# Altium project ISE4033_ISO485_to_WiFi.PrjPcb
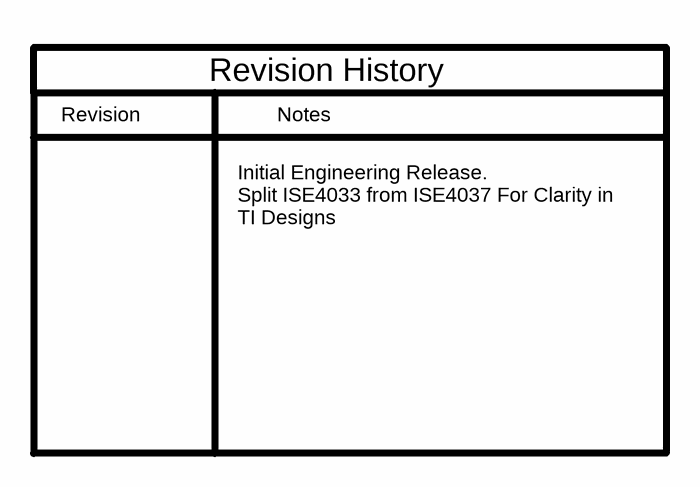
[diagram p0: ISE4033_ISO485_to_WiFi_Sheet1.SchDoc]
TID: TIDA-00486; TechSupport: http://www.ti.com/support; SCH_Rev: E1; PRJ_Title: Isolated RS-485 To Wi-Fi Bridge with 24 VAC Power; PRJ_Number: ISE4033; PRJ_Engineer: M. Knapp; PRJ_Customer: Public Release; PCB_Rev: E1; PCB_Layout: Krypton Solutions/RS; EVM_Orderable: N/A; CopyrightYear: 2015
6 sheets, 129 parts. Net scope: global (net labels, ports and power ports of the same name join across sheets).
Board file: ISE4033_ISO485_to_WiFi.PcbDoc
Sheets:
  ISE4033_ISO485_to_WiFi_Sheet1.SchDoc
  ISE4033_ISO485_to_WiFi_Sheet2.SchDoc
  ISE4033_ISO485_to_WiFi_Sheet3.SchDoc
  ISE4033_ISO485_to_WiFi_Sheet4.SchDoc
  ISE4033_ISO485_to_WiFi_Sheet5.SchDoc
  ISE4033E2_Sheet6.SchDoc

## Sheet ISE4033_ISO485_to_WiFi_Sheet1.SchDoc
size 431 x 279 mm; Date: Not shown in title block; ApprovedBy: Not shown in title block; CheckedBy: Not shown in title block; Author: Not shown in title block; CompanyName: Not shown in title block; Engineer: Not shown in title block; Organization: Not shown in title block; Address1: Not shown in title block; Address2: Not shown in title block; Address3: Not shown in title block; Address4: Not shown in title block; DocumentNumber: 1; Revision: Use project parameter SCH_Rev; SheetNumber: 1; SheetTotal: 6; PageSetup: Record=PageOptions¦CenterHorizontal=True¦CenterVertical=True¦PrintScale=1.00¦XCorrection=1.00¦YCorrection=1.00¦PrintKind=0¦BorderSize=5000000¦LeftOffset=0¦BottomOffset=0¦Orientation=2¦PaperLength=1000¦PaperWidth=1000¦Scale=100¦PaperSource=15¦PrintQuality=-3¦MediaType=1¦DitherType=10¦PrintScaleMode=1¦PaperKind=Tabloid (11 x 17")¦PaperIndex=17

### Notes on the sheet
- Revision
- Notes
- Revision History
- Initial Engineering Release.
  Split ISE4033 from ISE4037 For Clarity in
  TI Designs

## Sheet ISE4033_ISO485_to_WiFi_Sheet2.SchDoc
size 431 x 279 mm; Date: Not shown in title block; ApprovedBy: Not shown in title block; CheckedBy: Not shown in title block; Author: Not shown in title block; CompanyName: Not shown in title block; Engineer: Not shown in title block; Organization: Not shown in title block; Address1: Not shown in title block; Address2: Not shown in title block; Address3: Not shown in title block; Address4: Not shown in title block; DocumentNumber: 1; Revision: Use project parameter SCH_Rev; SheetNumber: 2; SheetTotal: 6; PageSetup: Record=PageOptions¦CenterHorizontal=True¦CenterVertical=True¦PrintScale=1.00¦XCorrection=1.00¦YCorrection=1.00¦PrintKind=0¦BorderSize=5000000¦LeftOffset=0¦BottomOffset=0¦Orientation=2¦PaperLength=1000¦PaperWidth=1000¦Scale=100¦PaperSource=15¦PrintQuality=-3¦MediaType=1¦DitherType=10¦PrintScaleMode=1¦PaperKind=Tabloid (11 x 17")¦PaperIndex=17
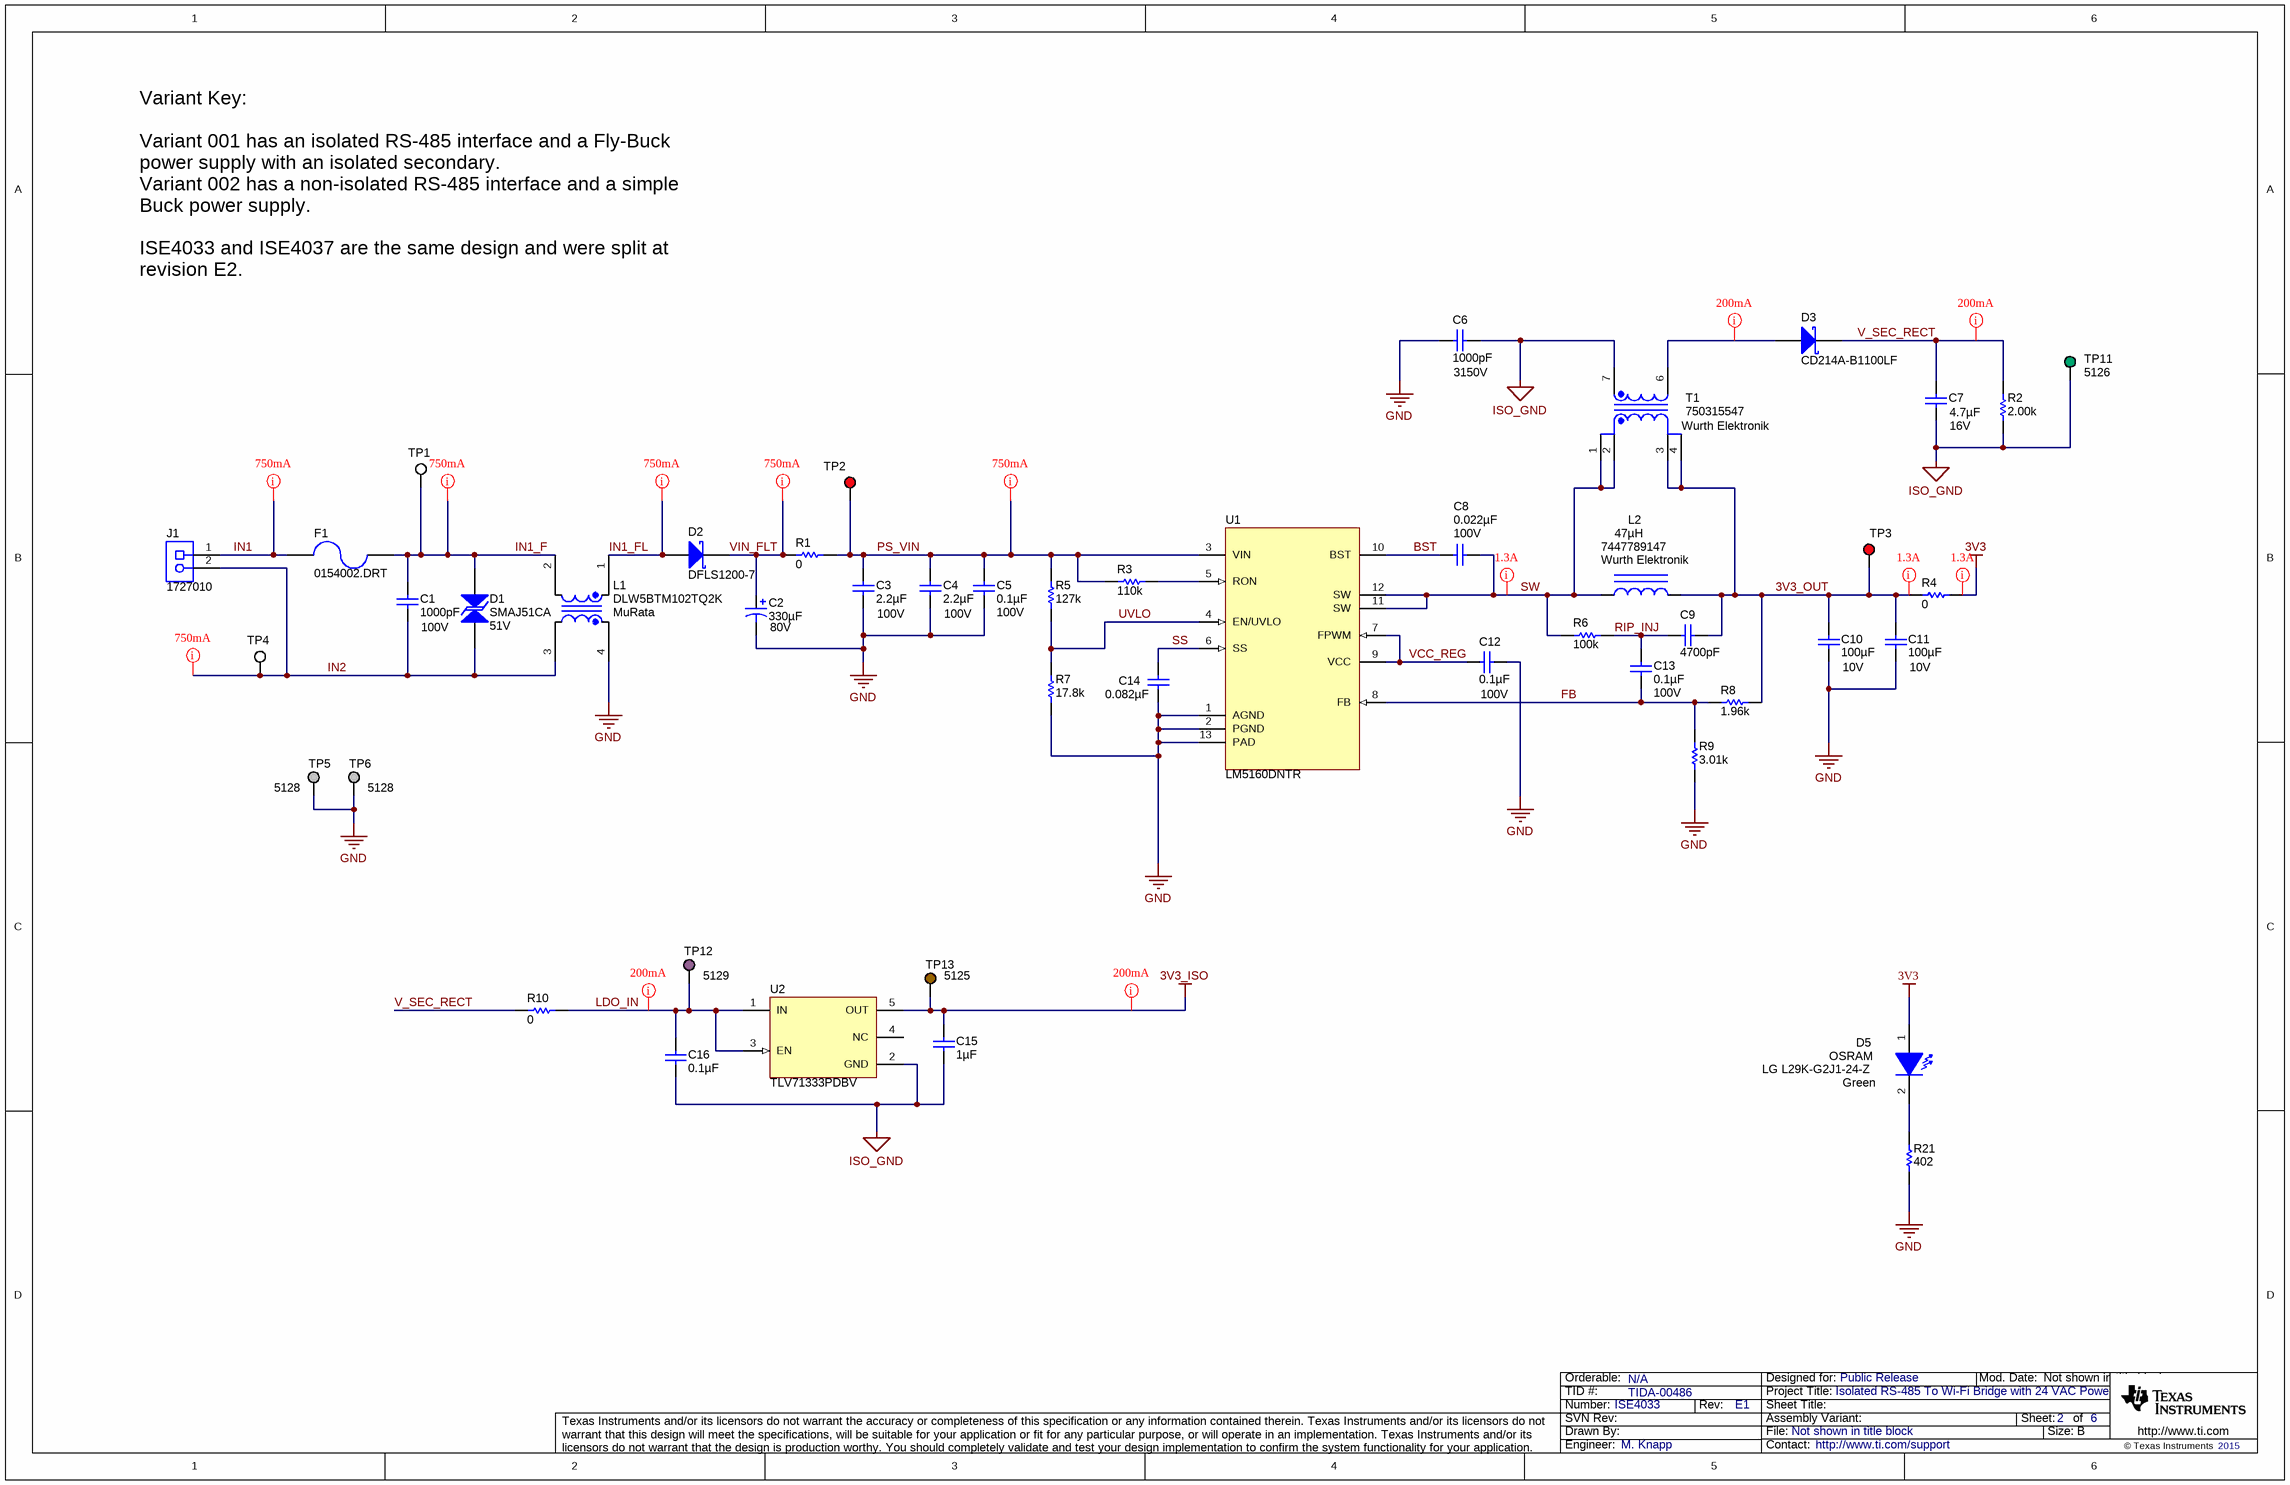
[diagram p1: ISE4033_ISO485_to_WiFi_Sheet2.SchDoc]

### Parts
C1  ValueDisplayed: 1000pF  Value2: 100V  [0603]  (hidden comment: 06031C102KAT2A)
C2  ValueDisplayed: 330µF  Value2: 80V  [SM_RADIAL_J16]  (hidden comment: EEV-FK1K331M)
C3  ValueDisplayed: 2.2µF  Value2: 100V  [1210]  (hidden comment: C1210C225K1RACTU)
C4  ValueDisplayed: 2.2µF  Value2: 100V  [1210]  (hidden comment: C1210C225K1RACTU)
C5  ValueDisplayed: 0.1µF  Value2: 100V  [0805_HV]  (hidden comment: C0805C104K1RACTU)
C6  ValueDisplayed: 1000pF  Value2: 3150V  [CAPRD750W60D700H1000]  (hidden comment: DEBE33F102ZC3B)
C7  ValueDisplayed: 4.7µF  Value2: 16V  [1206]  (hidden comment: C3216X7R1C475K)
C8  ValueDisplayed: 0.022µF  Value2: 100V  [0805_HV]  (hidden comment: 08051C223KAT2A)
C9  ValueDisplayed: 4700pF  [0603]  (hidden comment: 06031C472KAT2A)
C10  ValueDisplayed: 100µF  Value2: 10V  [1210_280]  (hidden comment: C1210C107M8PACTU)
C11  ValueDisplayed: 100µF  Value2: 10V  [1210_280]  (hidden comment: C1210C107M8PACTU)
C12  ValueDisplayed: 0.1µF  Value2: 100V  [0805_HV]  (hidden comment: C0805C104K1RACTU)
C13  ValueDisplayed: 0.1µF  Value2: 100V  [0805_HV]  (hidden comment: C0805C104K1RACTU)
C14  ValueDisplayed: 0.082µF  [0805_HV]  (hidden comment: C0805C823K1RACTU)
C15  ValueDisplayed: 1µF  [0603]  (hidden comment: GRM188R71A105KA61D)
C16  ValueDisplayed: 0.1µF  [0402]  (hidden comment: GRM155R71A104KA01D)
D1  SMAJ51CA  value 51V  [SMA]
D2  DFLS1200-7  [powerDI123]
D3  CD214A-B1100LF  [SMA]
D5  value Green  Manufacturer: OSRAM  [LG L29K_GREEN]  (hidden comment: LG L29K-G2J1-24-Z)
F1  0154002.DRT  [FUSE_154]
J1  1727010  [PhoenixConact_1727010]
L1  DLW5BTM102TQ2K  Manufacturer: MuRata  [DLW5BT_TQ2]
L2  7447789147  Manufacturer: Wurth Elektronik  ValueDisplayed: 47µH  [WE-PD-S]
R1  ValueDisplayed: 0  [2010]  (hidden comment: CRCW20100000Z0EF)
R2  ValueDisplayed: 2.00k  [0402]  (hidden comment: CRCW04022K00FKED)
R3  ValueDisplayed: 110k  [0402]  (hidden comment: CRCW0402110KFKED)
R4  ValueDisplayed: 0  [2010]  (hidden comment: CRCW20100000Z0EF)
R5  ValueDisplayed: 127k  [0402]  (hidden comment: CRCW0402127KFKED)
R6  ValueDisplayed: 100k  [0402]  (hidden comment: CRCW0402100KFKED)
R7  ValueDisplayed: 17.8k  [0402]  (hidden comment: CRCW040217K8FKED)
R8  ValueDisplayed: 1.96k  [0402]  (hidden comment: CRCW04021K96FKED)
R9  ValueDisplayed: 3.01k  [0402]  (hidden comment: CRCW04023K01FKED)
R10  ValueDisplayed: 0  [0603]  (hidden comment: CRCW06030000Z0EA)
R21  ValueDisplayed: 402  [0402]  (hidden comment: CRCW0402402RFKED)
T1  750315547  Manufacturer: Wurth Elektronik  [Wurth_750315547_48]
TP1  5002  [Keystone5002]  (value not drawn)
TP2  5000  [Keystone5000]  (value not drawn)
TP3  5000  [Keystone5000]  (value not drawn)
TP4  5002  [Keystone5002]  (value not drawn)
TP5  5128  [Keystone5128]
TP6  5128  [Keystone5128]
TP11  5126  [Keystone5126]
TP12  5129  [Keystone5129]
TP13  5125  [Keystone5125]
U1  LM5160DNTR  [DNT0012B]
U2  TLV71333PDBV  [DBV0005A_N]

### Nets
3V3: D5.1(A) R4.2
3V3_ISO: C15.1 TP13.1 U2.5(OUT)
GND: C2.2(-) C3.2 C4.2 C5.2 C6.2 C10.2 C11.2 C12.2 C14.2 L1.4 R7.1 R9.1 R21.1 TP5.1 TP6.1 U1.1(AGND) U1.2(PGND) U1.13(PAD)
ISO_GND: C6.1 C7.2 C15.2 C16.2 R2.1 T1.7 TP11.1 U2.2(GND)
3V3_OUT: C9.1 C10.1 C11.1 L2.2 R4.1 R8.2 T1.3 T1.4 TP3.1
BST: C8.2 U1.10(BST)
FB: C13.2 R8.1 R9.2 U1.8(FB)
IN1: F1.2 J1.1
IN1_F: C1.1 D1.2 F1.1 L1.2 TP1.1
IN1_FL: D2.2(A) L1.1
IN2: C1.2 D1.1 J1.2 L1.3 TP4.1
LDO_IN: C16.1 R10.2 TP12.1 U2.1(IN) U2.3(EN)
PS_VIN: C3.1 C4.1 C5.1 R1.2 R3.1 R5.2 TP2.1 U1.3(VIN)
RIP_INJ: C9.2 C13.1 R6.2
SS: C14.1 U1.6(SS)
SW: C8.1 L2.1 R6.1 T1.1 T1.2 U1.11(SW) U1.12(SW)
UVLO: R5.1 R7.2 U1.4(EN/UVLO)
V_SEC_RECT: C7.1 D3.1(K) R2.2 R10.1
VCC_REG: C12.1 U1.7(FPWM) U1.9(VCC)
VIN_FLT: C2.1(+) D2.1(K) R1.1
NetD3_2: D3.2(A) T1.6
NetD5_2: D5.2(K) R21.2
NetR3_2: R3.2 U1.5(RON)

Not connected (* = marked no-connect by the designer): U2 4(NC)

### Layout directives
750mA: 750mA: 3V3, 3V3_ISO, 3V3_OUT, IN1, IN1_F, IN1_FL, IN2, LDO_IN, NetD3_2, PS_VIN, SW, V_SEC_RECT, VIN_FLT

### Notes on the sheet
- Variant Key:
  Variant 001 has an isolated RS-485 interface and a Fly-Buck power supply with an isolated secondary.
  Variant 002 has a non-isolated RS-485 interface and a simple Buck power supply.
  ISE4033 and ISE4037 are the same design and were split at revision E2.

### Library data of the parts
C1 = 06031C102KAT2A: CAP, CERM, 1000 pF, 100 V, +/- 10%, X7R, 0603; Manufacturer: AVX; Polarized: N; CompType: Capacitor; Value: 1000pF; U/M: EA; Cap_F: 0.000000001; Tolerance_%: 10; ESR_ohm: 0.276; Value1: 0.276 ohm; VDC_V: 100; TaMin_C: -55; TaMax_C: 125
C2 = EEV-FK1K331M: CAP, AL, 330 µF, 80 V, +/- 20%, 0.17 ohm, SMD; Manufacturer: Panasonic; Polarized: Y; CompType: Capacitor; Value: 330uF; U/M: EA; Cap_F: 0.00033; Tolerance_%: 20; VDC_V: 80; ESR_ohm: 0.17; IRMS_A: 0.793; TaMin_C: -55; TaMax_C: 105; Cap_Case: J16
C3 C4 = C1210C225K1RACTU: CAP, CERM, 2.2 µF, 100 V, +/- 10%, X7R, 1210; Manufacturer: Kemet; Polarized: N; CompType: Capacitor; Value: 2.2uF; U/M: EA; Cap_F: 0.0000022; Tolerance_%: 10; Value1: Unknown; VDC_V: 100; TaMin_C: -55; TaMax_C: 125
C5 C12 C13 = C0805C104K1RACTU: CAP, CERM, 0.1 µF, 100 V, +/- 10%, X7R, 0805; Manufacturer: Kemet; Polarized: N; CompType: Capacitor; Value: 0.1uF; U/M: EA; Cap_F: 0.0000001; Tolerance_%: 10; ESR_ohm: 0.064; Value1: 0.064 ohm; VDC_V: 100; IRMS_A: 1.64; TaMin_C: -55; TaMax_C: 125; Cap_Case: 0805
C6 = DEBE33F102ZC3B: CAP, CERM, 1000 pF, 3150 V, +80/-20%, E, Radial Disc D7x6mm; Manufacturer: MuRata; Polarized: N; CompType: Capacitor; Value: 1000pF; U/M: EA; Cap_F: 0.000000001; Tolerance_%: 80; Value1: Unknown; VDC_V: 3150; TaMin_C: -25; TaMax_C: 85; Cap_Case: Disc, 7x6mm
C7 = C3216X7R1C475K: CAP, CERM, 4.7 µF, 16 V, +/- 10%, X7R, 1206; Manufacturer: TDK; Polarized: N; CompType: Capacitor; Value: 4.7uF; U/M: EA; Cap_F: 0.0000047; Tolerance_%: 10; ESR_ohm: 0.0036; Value1: 0.0036 ohm; VDC_V: 16; IRMS_A: 2; TaMin_C: -55; TaMax_C: 125
C8 = 08051C223KAT2A: CAP, CERM, 0.022 µF, 100 V, +/- 10%, X7R, 0805; Manufacturer: AVX; Polarized: N; CompType: Capacitor; Value: 0.022uF; U/M: EA; Cap_F: 0.000000022; Tolerance_%: 10; ESR_ohm: 0.052; Value1: 0.052 ohm; VDC_V: 100; TaMin_C: -55; TaMax_C: 125; Cap_Case: 0805
C9 = 06031C472KAT2A: CAP, CERM, 4700 pF, 100 V, +/- 10%, X7R, 0603; Manufacturer: AVX; Polarized: N; CompType: Capacitor; Value: 4700pF; U/M: EA; Cap_F: 0.0000000047; Tolerance_%: 10; ESR_ohm: 0.136; Value1: 0.136 ohm; VDC_V: 100; Value2: 100V; TaMin_C: -55; TaMax_C: 125
C10 C11 = C1210C107M8PACTU: CAP, CERM, 100 µF, 10 V, +/- 20%, X5R, 1210; Manufacturer: Wurth Elektronik; Polarized: N; CompType: Capacitor; Value: 100uF; U/M: EA; Cap_F: 0.0001; Tolerance_%: 20; Value1: Unknown; VDC_V: 10; TaMin_C: -55; TaMax_C: 85; Cap_Case: 1210
C14 = C0805C823K1RACTU: CAP, CERM, 0.082 µF, 100 V, +/- 10%, X7R, 0805; Manufacturer: Kemet; Polarized: N; CompType: Capacitor; Value: 0.082uF; U/M: EA; Cap_F: 0.000000082; Tolerance_%: 10; ESR_ohm: 0.071; Value1: 0.071 ohm; VDC_V: 100; Value2: 100V; IRMS_A: 1.44; TaMin_C: -55; TaMax_C: 125; Cap_Case: 0805
C15 = GRM188R71A105KA61D: CAP, CERM, 1 µF, 10 V, +/- 10%, X7R, 0603; Manufacturer: MuRata; Polarized: N; CompType: Capacitor; Value: 1uF; U/M: EA; Cap_F: 0.000001; Tolerance_%: 10; ESR_ohm: 0.011; Value1: 0.011 ohm; Value2: 10V; TaMin_C: -55; TaMax_C: 125
C16 = GRM155R71A104KA01D: CAP, CERM, 0.1 µF, 10 V, +/- 10%, X7R, 0402; Manufacturer: MuRata; Polarized: N; CompType: Capacitor; Value: 0.1uF; U/M: EA; Cap_F: 0.0000001; Tolerance_%: 10; Value1: Unknown; Value2: 10V; TaMin_C: -55; TaMax_C: 125
D1 = SMAJ51CA: Diode, TVS, Bi, 51 V, 400 W, SMA; Manufacturer: Littelfuse; U/M: EA; Power_W: 400; Vr_V: 51; Value1: 400W; RJA_CperW: 120
D2 = DFLS1200-7: Diode, Schottky, 200 V, 1 A, PowerDI123; Manufacturer: Diodes Inc.; U/M: EA; Vf_V: 0.85; Value: 200V; Value1: 1A; Value2: 0.85V; Io_A: 1; Vr_V: 200; TJmax_C: 175; RJC_CperW: 7
D3 = CD214A-B1100LF: Diode, Schottky, 100 V, 1 A, SMA; Manufacturer: Bourns; U/M: EA; Vf_V: 0.79; Value: 100V; Value1: 1A; Value2: 0.79V; Io_A: 1; Vr_V: 100; TJmax_C: 125; RJC_CperW: 25
D5 = LG L29K-G2J1-24-Z: LED, Green, SMD; Vf_V: 1.7; Value2: 1.7V; Io_A: 0.002; Tjmax_C: 110; Value1: W; U/M: EA
F1 = 0154002.DRT: Fuse, 2 A, 125 V, SMD; Manufacturer: Littelfuse; U/M: EA; VDC_V: 125; Interrupt_AC: 50; Irating_A: 2; Rtyp_Ohm: 0.0625; MeltingTyp: 8.2; Soldering_Reflow_MaxTemp_C: 260; Soldering_Reflow_MaxTime_s: 40
J1 = 1727010: Conn Term Block, 2POS, 3.81mm, TH; Manufacturer: Phoenix Contact; SymbolCreator: a0412235; CompType: Terminal Block; U/M: EA; Value: 2x1
L1 = DLW5BTM102TQ2K: Coupled inductor, 2.5 A, 0.034 ohm, SMD; SymbolCreator: a0412235; Isat: 2.5; DCR_ohm: 0.034
L2 = 7447789147: Inductor, Shielded Drum Core, Ferrite, 47 µH, 0.85 A, 0.315 ohm, SMD; Ind_H: 47.0E-6; Value: 47uH; Imax_A: 0.85; Irms: 0.85A @ 40C rise; Isat: 1A @ 10% inductance drop; DCR_ohm: 0.315; Value2: 0.85A
R1 R4 = CRCW20100000Z0EF: RES, 0, 5%, 0.75 W, 2010; Manufacturer: Vishay-Dale; CompType: Resistor; Value: 0; Value_Code: 0000; Tolerance_%: 5; Power_W: 0.75; Value2: 0.75W; TempCo: ppm/C; EIA_Code: E24; U/M: EA
R2 = CRCW04022K00FKED: RES, 2.00 k, 1%, 0.063 W, 0402; Manufacturer: Vishay-Dale; CompType: Resistor; Value: 2.00k; Res_ohm: 2000; Value_Code: 2k00; Tolerance_%: 1; Power_W: 0.063; Value2: 0.063W; VDC_V: 50; TempCo: 100 ppm/C; EIA_Code: E96; U/M: EA
R3 = CRCW0402110KFKED: RES, 110 k, 1%, 0.063 W, 0402; Manufacturer: Vishay-Dale; CompType: Resistor; Value: 110k; Res_ohm: 110000; Tolerance_%: 1; Power_W: 0.063; Value2: 0.063W; VDC_V: 50; TempCo: 100 ppm/C; EIA_Code: E96; U/M: EA
R5 = CRCW0402127KFKED: RES, 127 k, 1%, 0.063 W, 0402; Manufacturer: Vishay-Dale; CompType: Resistor; Value: 127k; Res_ohm: 127000; Tolerance_%: 1; Power_W: 0.063; Value2: 0.063W; VDC_V: 50; TempCo: 100 ppm/C; EIA_Code: E96; U/M: EA
R6 = CRCW0402100KFKED: RES, 100 k, 1%, 0.063 W, 0402; Manufacturer: Vishay-Dale; CompType: Resistor; Value: 100k; Res_ohm: 100000; Tolerance_%: 1; Power_W: 0.063; Value2: 0.063W; VDC_V: 50; TempCo: 100 ppm/C; EIA_Code: E96; U/M: EA
R7 = CRCW040217K8FKED: RES, 17.8 k, 1%, 0.063 W, 0402; Manufacturer: Vishay-Dale; CompType: Resistor; Value: 17.8k; Res_ohm: 17800; Value_Code: 17k8; Tolerance_%: 1; Power_W: 0.063; Value2: 0.063W; VDC_V: 50; TempCo: 100 ppm/C; EIA_Code: E96; U/M: EA
R8 = CRCW04021K96FKED: RES, 1.96 k, 1%, 0.063 W, 0402; Manufacturer: Vishay-Dale; CompType: Resistor; Value: 1.96k; Res_ohm: 1960; Value_Code: 1k96; Tolerance_%: 1; Power_W: 0.063; Value2: 0.063W; VDC_V: 50; TempCo: 100 ppm/C; EIA_Code: E96; U/M: EA
R9 = CRCW04023K01FKED: RES, 3.01 k, 1%, 0.063 W, 0402; Manufacturer: Vishay-Dale; CompType: Resistor; Value: 3.01k; Res_ohm: 3010; Value_Code: 3k01; Tolerance_%: 1; Power_W: 0.063; Value2: 0.063W; VDC_V: 50; TempCo: 100 ppm/C; EIA_Code: E96; U/M: EA
R10 = CRCW06030000Z0EA: RES, 0, 5%, 0.1 W, 0603; Manufacturer: Vishay-Dale; CompType: Resistor; Value: 0; Value_Code: 0000; Tolerance_%: 5; Power_W: 0.1; Value2: 0.1W; VDC_V: 75; TempCo: 200 ppm/C; EIA_Code: E24; U/M: EA
R21 = CRCW0402402RFKED: RES, 402, 1%, 0.063 W, 0402; Manufacturer: Vishay-Dale; CompType: Resistor; Value: 402; Value_Code: 402R; Tolerance_%: 1; Power_W: 0.063; Value2: 0.063W; VDC_V: 50; TempCo: 100 ppm/C; EIA_Code: E96; U/M: EA
T1 = 750315547: Transformer, 42 uH, SMT; SymbolCreator: Altium; DCR_Ohm: 0.066; Value: 42 uH; U/M: EA
TP1 TP4 = 5002: Test Point, Miniature, White, TH; Manufacturer: Keystone; CompType: Test Point Loop; U/M: EA
TP2 TP3 = 5000: Test Point, Miniature, Red, TH; Manufacturer: Keystone; CompType: Test Point Loop; U/M: EA
TP5 TP6 = 5128: Test Point, Multipurpose, Grey, TH; Manufacturer: Keystone; CompType: Test Point Loop; U/M: EA; SymbolCreator: a0412235
TP11 = 5126: Test Point, Multipurpose, Green, TH; Manufacturer: Keystone; SymbolCreator: a0412235; CompType: Test Point Loop; U/M: EA
TP12 = 5129: Test Point, Multipurpose, Purple, TH; Manufacturer: Keystone; SymbolCreator: a0412235; CompType: Test Point Loop; U/M: EA
TP13 = 5125: Test Point, Multipurpose, Brown, TH; Manufacturer: Keystone; SymbolCreator: a0412235; CompType: Test Point Loop; U/M: EA
U1 = LM5160DNTR: Wide Input 65V, 1.5A Synchronous Step-Down DC-DC Converter, DNT0012B; Alternate PartNumber: LM5160DNTT; Manufacturer: Texas Instruments; SymbolCreator: a0411947; CompType: IC; U/M: EA
U2 = TLV71333PDBV: Capacitor-Free, 150-mA, Low-Dropout Regulator with Foldback Current Limit for Portable Devices, DBV0005A; Manufacturer: Texas Instruments; SymbolCreator: Altium; CompType: IC; U/M: EA

## Sheet ISE4033_ISO485_to_WiFi_Sheet3.SchDoc
size 431 x 279 mm; Date: Not shown in title block; ApprovedBy: Not shown in title block; CheckedBy: Not shown in title block; Author: Not shown in title block; CompanyName: Not shown in title block; Engineer: Not shown in title block; Organization: Not shown in title block; Address1: Not shown in title block; Address2: Not shown in title block; Address3: Not shown in title block; Address4: Not shown in title block; DocumentNumber: 1; Revision: Use project parameter SCH_Rev; SheetNumber: 3; SheetTotal: 6; PageSetup: Record=PageOptions¦CenterHorizontal=True¦CenterVertical=True¦PrintScale=1.00¦XCorrection=1.00¦YCorrection=1.00¦PrintKind=0¦BorderSize=5000000¦LeftOffset=0¦BottomOffset=0¦Orientation=2¦PaperLength=1000¦PaperWidth=1000¦Scale=100¦PaperSource=15¦PrintQuality=-3¦MediaType=1¦DitherType=10¦PrintScaleMode=1¦PaperKind=Tabloid (11 x 17")¦PaperIndex=17
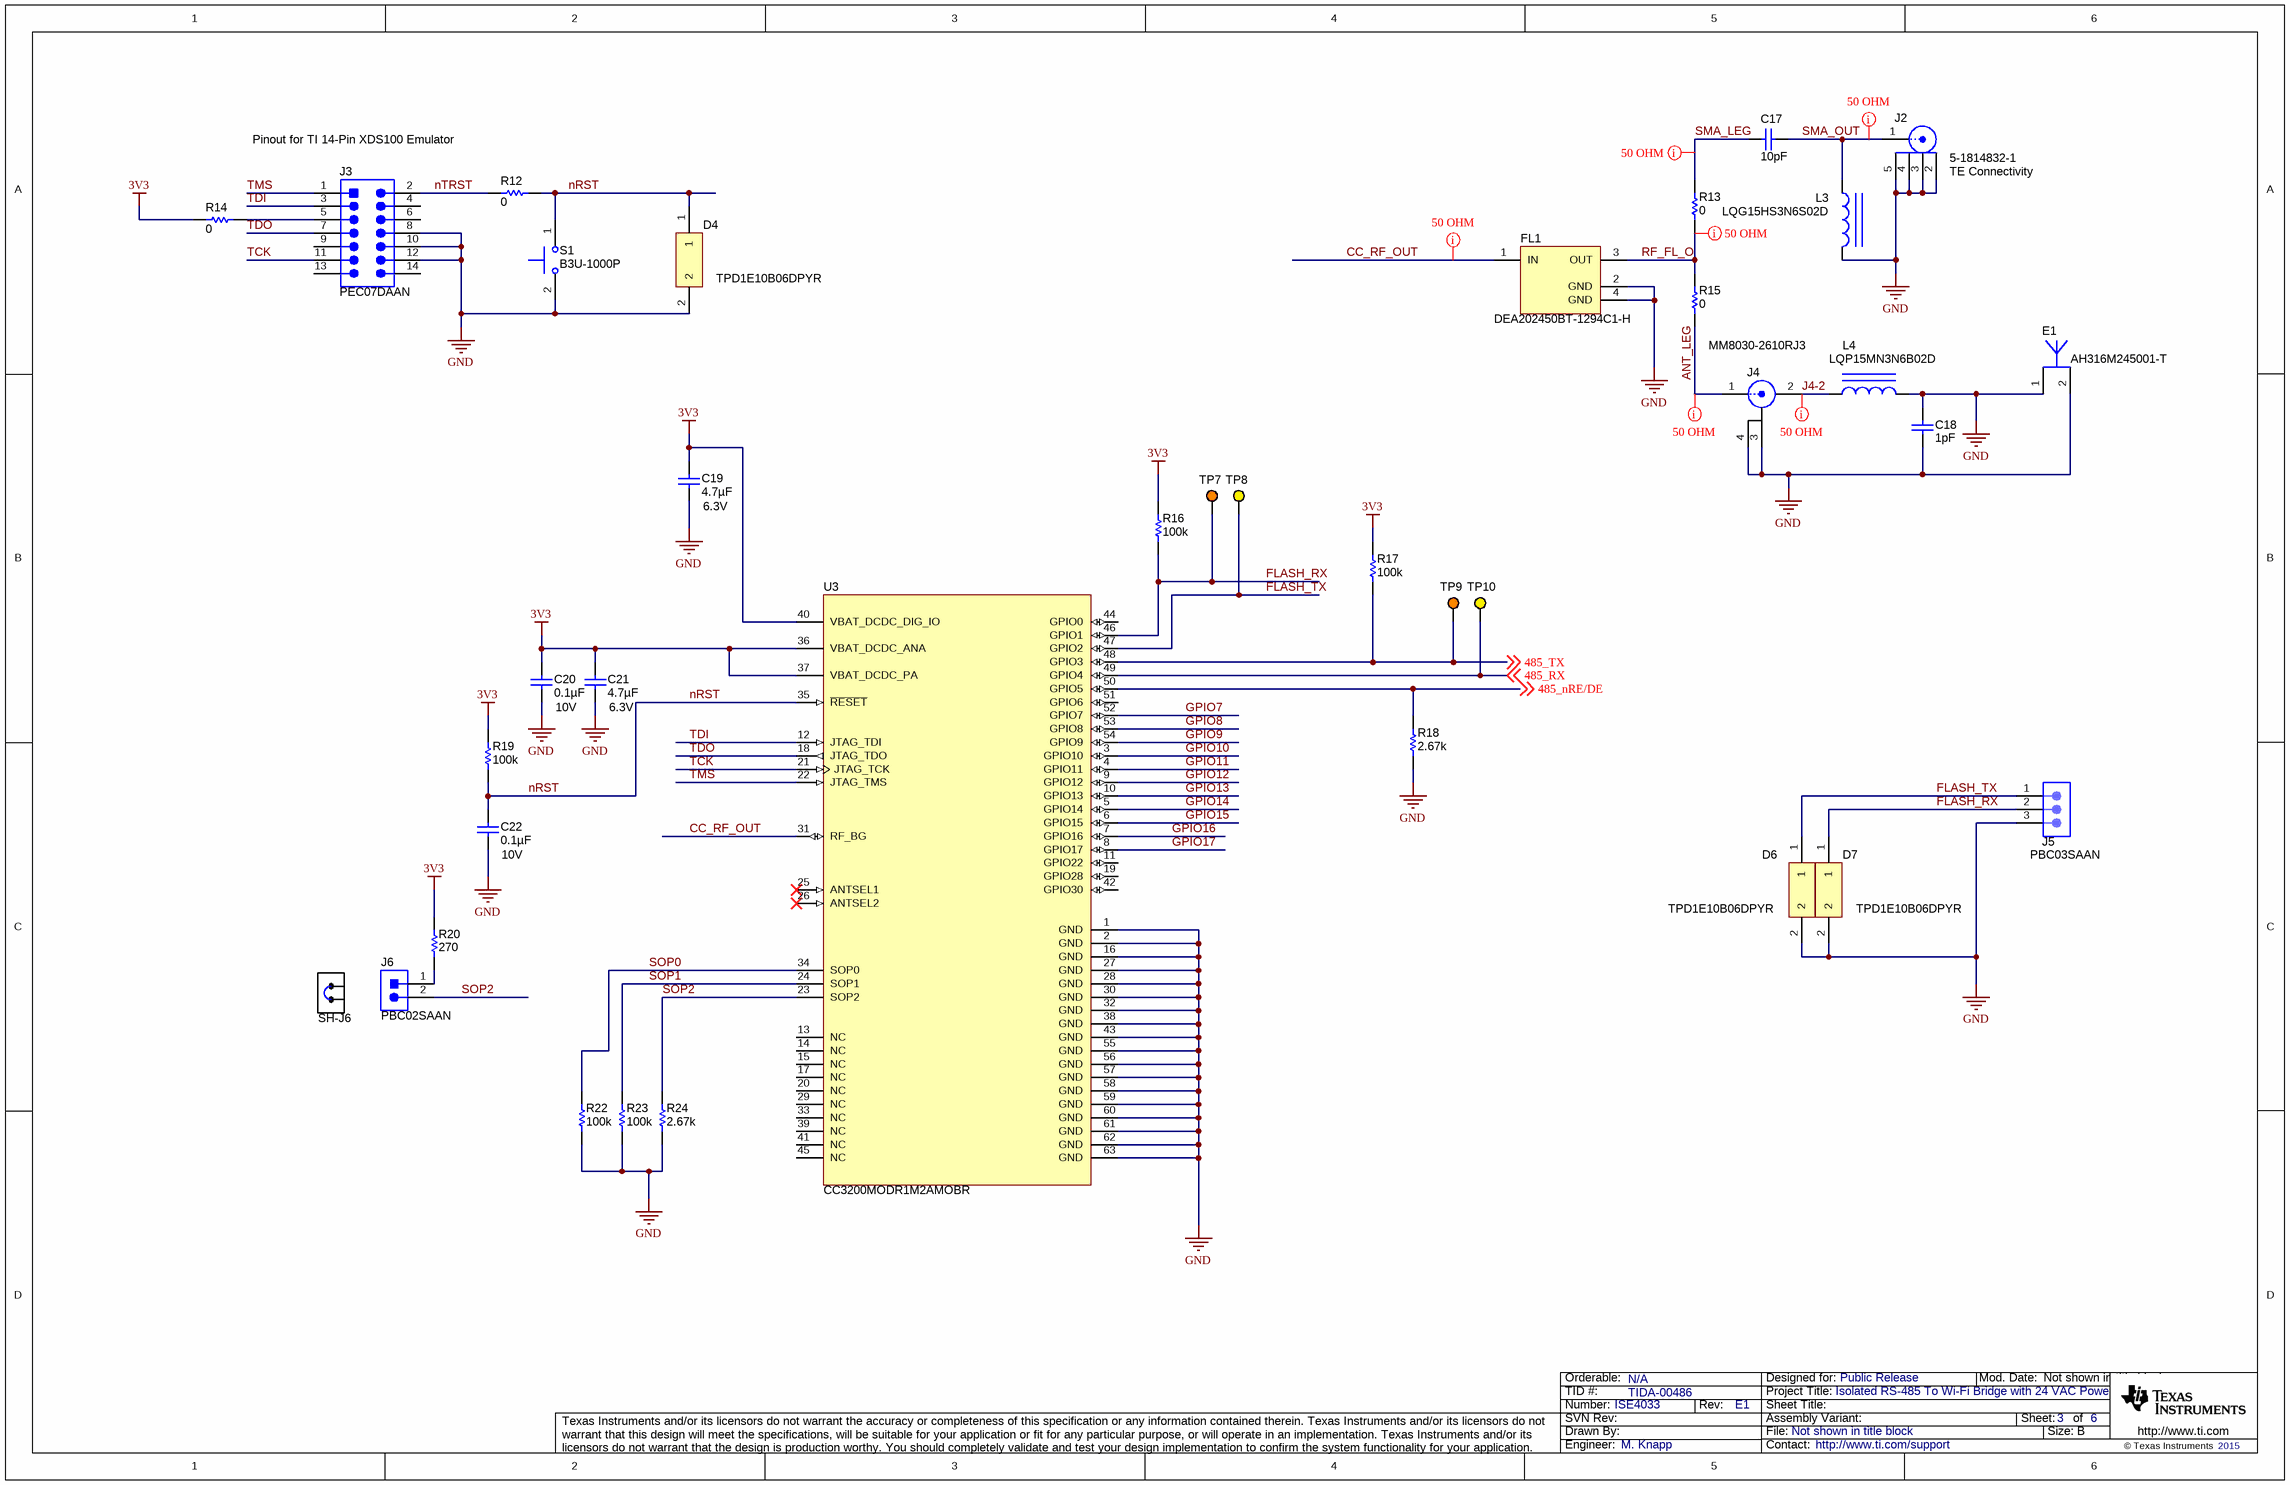
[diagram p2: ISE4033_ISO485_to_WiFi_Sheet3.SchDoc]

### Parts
C17  ValueDisplayed: 10pF  [0402]  (hidden comment: GRM1555C1H100JA01D)
C18  ValueDisplayed: 1pF  [0402L]  (hidden comment: GRM1555C1H1R0BA01D)
C19  ValueDisplayed: 4.7µF  Value2: 6.3V  [0402]  (hidden comment: GRM155R60J475ME87D)
C20  ValueDisplayed: 0.1µF  Value2: 10V  [0402]  (hidden comment: GRM155R71A104KA01D)
C21  ValueDisplayed: 4.7µF  Value2: 6.3V  [0402]  (hidden comment: GRM155R60J475ME87D)
C22  ValueDisplayed: 0.1µF  Value2: 10V  [0402]  (hidden comment: GRM155R71A104KA01D)
D4  TPD1E10B06DPYR  [DPY0002A]
D6  TPD1E10B06DPYR  [DPY0002A]
D7  TPD1E10B06DPYR  [DPY0002A]
E1  AH316M245001-T  [TAYO_AH316M]
FL1  DEA202450BT-1294C1-H  [TDK_DEA202450BT-1294C1-H]
J2  5-1814832-1  Manufacturer: TE Connectivity  [TE_5-1814832-1]
J3  PEC07DAAN  [CONN_PEC07DAAN]
J4  MM8030-2610RJ3  [MuRata_MM8030-2610]
J5  PBC03SAAN  [PBC03SAAN]
J6  PBC02SAAN  [Sullins_PBC02SAAN]
L3  LQG15HS3N6S02D  [IND_LQG15H]
L4  LQP15MN3N6B02D  [LQP_0402]
R12  ValueDisplayed: 0  [0402]  (hidden comment: CRCW04020000Z0ED)
R13  ValueDisplayed: 0  [0402L]  (hidden comment: CRCW04020000Z0ED)
R14  ValueDisplayed: 0  [0402]  (hidden comment: CRCW04020000Z0ED)
R15  ValueDisplayed: 0  [0402L]  (hidden comment: CRCW04020000Z0ED)
R16  ValueDisplayed: 100k  [0402]  (hidden comment: CRCW0402100KFKED)
R17  ValueDisplayed: 100k  [0402]  (hidden comment: CRCW0402100KFKED)
R18  ValueDisplayed: 2.67k  [0402]  (hidden comment: CRCW04022K67FKED)
R19  ValueDisplayed: 100k  [0402]  (hidden comment: CRCW0402100KFKED)
R20  ValueDisplayed: 270  [0402]  (hidden comment: CRCW0402270RJNED)
R22  ValueDisplayed: 100k  [0402]  (hidden comment: CRCW0402100KFKED)
R23  ValueDisplayed: 100k  [0402]  (hidden comment: CRCW0402100KFKED)
R24  ValueDisplayed: 2.67k  [0402]  (hidden comment: CRCW04022K67FKED)
S1  B3U-1000P  [SW_B3U-1000P]
SH-J6  881545-2  [TE_881545-2]  (value not drawn)  (mechanical)
TP7  5003  [Keystone5003]  (value not drawn)
TP8  5004  [Keystone5004]  (value not drawn)
TP9  5003  [Keystone5003]  (value not drawn)
TP10  5004  [Keystone5004]  (value not drawn)
U3  CC3200MODR1M2AMOBR  [MOB0063A]

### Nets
3V3: C19.1 C20.1 C21.1 R14.2 R16.2 R17.2 R19.2 R20.2 U3.36(VBAT_DCDC_ANA) U3.37(VBAT_DCDC_PA) U3.40(VBAT_DCDC_DIG_IO)
GND: C18.1 C18.2 C19.2 C20.2 C21.2 C22.2 D4.2 D6.2 D7.2 E1.1 E1.2 FL1.2(GND) FL1.4(GND) J2.2 J2.3 J2.4 J2.5 J3.8 J3.10 J3.12 J4.3(GND) J4.4(GND) J5.3 L3.1 L4.2 R18.1 R22.1 R23.1 R24.1 S1.2 U3.1(GND) U3.2(GND) U3.16(GND) U3.27(GND) U3.28(GND) U3.30(GND) U3.32(GND) U3.38(GND) U3.43(GND) U3.55(GND) U3.56(GND) U3.57(GND) U3.58(GND) U3.59(GND) U3.60(GND) U3.61(GND) U3.62(GND) U3.63(GND)
485_nRE/DE: R18.2 U3.50(GPIO5) ; off-sheet 485_nRE/DE
485_RX: TP10.1 U3.49(GPIO4) ; off-sheet 485_RX
485_TX: R17.1 TP9.1 U3.48(GPIO3) ; off-sheet 485_TX
ANT_LEG: J4.1(IN) R15.1
CC_RF_OUT: FL1.1(IN) U3.31(RF_BG)
FLASH_RX: D7.1 J5.2 R16.1 TP7.1 U3.46(GPIO1)
FLASH_TX: D6.1 J5.1 TP8.1 U3.47(GPIO2)
GPIO7: U3.52(GPIO7)
GPIO8: U3.53(GPIO8)
GPIO9: U3.54(GPIO9)
GPIO10: U3.3(GPIO10)
GPIO11: U3.4(GPIO11)
GPIO12: U3.9(GPIO12)
GPIO13: U3.10(GPIO13)
GPIO14: U3.5(GPIO14)
GPIO15: U3.6(GPIO15)
GPIO16: U3.7(GPIO16)
GPIO17: U3.8(GPIO17)
J4-2: J4.2(OUT) L4.1
nRST: C22.1 D4.1 R12.1 R19.1 S1.1 U3.35(~{RESET})
nTRST: J3.2 R12.2
RF_FL_O: FL1.3(OUT) R13.1 R15.2
SMA_LEG: C17.2 R13.2
SMA_OUT: C17.1 J2.1 L3.2
SOP0: R22.2 U3.34(SOP0)
SOP1: R23.2 U3.24(SOP1)
SOP2: J6.2 R24.2 U3.23(SOP2)
TCK: J3.11 U3.21(JTAG_TCK)
TDI: J3.3 U3.12(JTAG_TDI)
TDO: J3.7 U3.18(JTAG_TDO)
TMS: J3.1 U3.22(JTAG_TMS)
NetJ3_5: J3.5 R14.1
NetJ6_1: J6.1 R20.1

Not connected (* = marked no-connect by the designer): J3 4 6 9 13 14; U3 11(GPIO22) 13(NC) 14(NC) 15(NC) 17(NC) 19(GPIO28) 20(NC) 25(ANTSEL1)* 26(ANTSEL2)* 29(NC) 33(NC) 39(NC) 41(NC) 42(GPIO30) 44(GPIO0) 45(NC) 51(GPIO6)

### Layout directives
net class 50 OHM: ANT_LEG, CC_RF_OUT, J4-2, RF_FL_O, SMA_LEG, SMA_OUT

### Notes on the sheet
- Pinout for TI 14-Pin XDS100 Emulator

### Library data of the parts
C17 = GRM1555C1H100JA01D: CAP, CERM, 10 pF, 50 V, +/- 5%, C0G/NP0, 0402; Manufacturer: MuRata; Polarized: N; CompType: Capacitor; Value: 10pF; U/M: EA; Cap_F: 0.00000000001; Tolerance_%: 5; Value1: Unknown; VDC_V: 50; Value2: 50V; TaMin_C: -55; TaMax_C: 125
C18 = GRM1555C1H1R0BA01D: CAP, CERM, 1 pF, 50 V, +/- 10%, C0G/NP0, 0402; Manufacturer: MuRata; Polarized: N; CompType: Capacitor; Value: 1pF; U/M: EA; Cap_F: 0.000000000001; Tolerance_%: 10; Value1: Unknown; VDC_V: 50; Value2: 50V; TaMin_C: -55; TaMax_C: 125; Cap_Case: 0402
C19 C21 = GRM155R60J475ME87D: CAP, CERM, 4.7 µF, 6.3 V, +/- 20%, X5R, 0402; Manufacturer: MuRata; Polarized: N; CompType: Capacitor; Value: 4.7uF; U/M: EA; Cap_F: 0.0000047; Tolerance_%: 20; ESR_ohm: 0.009; Value1: 0.009 ohm; VDC_V: 6.3; IRMS_A: 1.22; TaMin_C: -55; TaMax_C: 85
C20 C22 = GRM155R71A104KA01D: CAP, CERM, 0.1 µF, 10 V, +/- 10%, X7R, 0402; Manufacturer: MuRata; Polarized: N; CompType: Capacitor; Value: 0.1uF; U/M: EA; Cap_F: 0.0000001; Tolerance_%: 10; Value1: Unknown; TaMin_C: -55; TaMax_C: 125
D4 D6 D7 = TPD1E10B06DPYR: ESD in 0402 Package with 10 pF Capacitance and 6 V Breakdown, 1 Channel, -40 to +125 degC, 2-pin X2SON (DPY), Green (RoHS & no Sb/Br); Manufacturer: Texas Instruments; Alternate Manufacturer: None; Alternate PartNumber: Equivalent; Breakdown Voltage(Min)(V): 6; Eco-Plan: TBD; IEC 61000-4-2 Air-Gap(+/- kV): 30; IO Capacitance(Typ)(pF): 10; SubFamily: ESD Solution
E1 = AH316M245001-T: ANT BLUETOOTH W-LAN ZIGBEE WIMAX, SMD; Manufacturer: Taiyo Yuden; SymbolCreator: a0411947; CompType: Antenna
FL1 = DEA202450BT-1294C1-H: Multilayer Chip Band Pass Filter For 2.4GHz W-LAN/Bluetooth, SMD; Manufacturer: TDK; SymbolCreator: Altium; Value: 1.02 dB
J2 = 5-1814832-1: SMA Straight PCB Socket Die Cast, 50 Ohm, TH; SymbolCreator: X0208326; CompType: JACK; U/M: EA
J3 = PEC07DAAN: Header, 100mil, 7x2, Tin, TH; Manufacturer: Sullins Connector Solutions; SymbolCreator: a0412235; U/M: EA
J4 = MM8030-2610RJ3: Coaxial Connectors with Switch, 50 Ohm, SMD; Manufacturer: MuRata; SymbolCreator: Altium; U/M: EA
J5 = PBC03SAAN: Header, 100mil, 3x1, Gold, TH; Manufacturer: Sullins Connector Solutions; U/M: EA; Value: 1x3
J6 = PBC02SAAN: Header, 100mil, 2x1, Gold, TH; Manufacturer: Sullins Connector Solutions; SymbolCreator: a0412235; U/M: EA
L3 = LQG15HS3N6S02D: Inductor, Multilayer, Air Core, 3.6 nH, 0.3 A, 0.18 ohm, SMD; Manufacturer: MuRata; Value: 3.6nH; Ind_H: 3.6E-9; Imax_A: 0.3; Irms: 0.3A @ C rise; Isat: 0.3A @ % inductance drop; DCR_ohm: 0.18; Value2: 0.3A
L4 = LQP15MN3N6B02D: Inductor, Film, 3.6 nH, 0.17 A, 0.5 ohm, SMD; Manufacturer: MuRata; Value: 3.6nH; Ind_H: 3.6E-9; Imax_A: 0.17; DCR_ohm: 0.5; Value1: 0.5 ohm; Value2: 0.17A
R12-R15 = CRCW04020000Z0ED: RES, 0, 5%, 0.063 W, 0402; Manufacturer: Vishay-Dale; CompType: Resistor; Value: 0; Value_Code: 0000; Tolerance_%: 5; Power_W: 0.063; Value2: 0.063W; VDC_V: 50; TempCo: 200 ppm/C; EIA_Code: E24; U/M: EA
R16 R17 R19 R22 R23 = CRCW0402100KFKED: as R6 on sheet ISE4033_ISO485_to_WiFi_Sheet2
R18 R24 = CRCW04022K67FKED: RES, 2.67 k, 1%, 0.063 W, 0402; Manufacturer: Vishay-Dale; CompType: Resistor; Value: 2.67k; Res_ohm: 2670; Value_Code: 2k67; Tolerance_%: 1; Power_W: 0.063; Value2: 0.063W; VDC_V: 50; TempCo: 100 ppm/C; EIA_Code: E96; U/M: EA
R20 = CRCW0402270RJNED: RES, 270, 5%, 0.063 W, 0402; Manufacturer: Vishay-Dale; CompType: Resistor; Value: 270; Value_Code: 270R; Tolerance_%: 5; Power_W: 0.063; Value2: 0.063W; VDC_V: 50; TempCo: 200 ppm/C; EIA_Code: E24; U/M: EA
S1 = B3U-1000P: SWITCH TACTILE SPST-NO 0.05A 12V; Manufacturer: Omron Electronic Components; SymbolCreator: a0412235; VDC_V: 12; SwitchFunction: Off-Mom; PositionCount: 1; CurrentRating_mA: 50
SH-J6 = 881545-2: Shunt, 100mil, Gold plated, Black; Manufacturer: TE Connectivity
TP7 TP9 = 5003: Test Point, Miniature, Orange, TH; Manufacturer: Keystone; CompType: Test Point Loop; U/M: EA
TP8 TP10 = 5004: Test Point, Miniature, Yellow, TH; Manufacturer: Keystone; CompType: Test Point Loop; U/M: EA
U3 = CC3200MODR1M2AMOBR: SimpleLink™ Wi-Fi ® and Internet-of-Things Module Solution, a Single-Chip Wireless MCU, MOB0063A; Alternate PartNumber: CC3200MODR1M2AMOBT; Manufacturer: Texas Instruments; SymbolCreator: Altium; CompType: IC; U/M: EA

## Sheet ISE4033_ISO485_to_WiFi_Sheet4.SchDoc
size 431 x 279 mm; Date: Not shown in title block; ApprovedBy: Not shown in title block; CheckedBy: Not shown in title block; Author: Not shown in title block; CompanyName: Not shown in title block; Engineer: Not shown in title block; Organization: Not shown in title block; Address1: Not shown in title block; Address2: Not shown in title block; Address3: Not shown in title block; Address4: Not shown in title block; DocumentNumber: 1; Revision: Use project parameter SCH_Rev; SheetNumber: 4; SheetTotal: 6; PageSetup: Record=PageOptions¦CenterHorizontal=True¦CenterVertical=True¦PrintScale=0.96¦XCorrection=1.00¦YCorrection=1.00¦PrintKind=0¦BorderSize=5000000¦LeftOffset=0¦BottomOffset=0¦Orientation=2¦PaperLength=1000¦PaperWidth=1000¦Scale=100¦PaperSource=15¦PrintQuality=-3¦MediaType=1¦DitherType=10¦PrintScaleMode=1¦PaperKind=Tabloid (11 x 17")¦PaperIndex=17
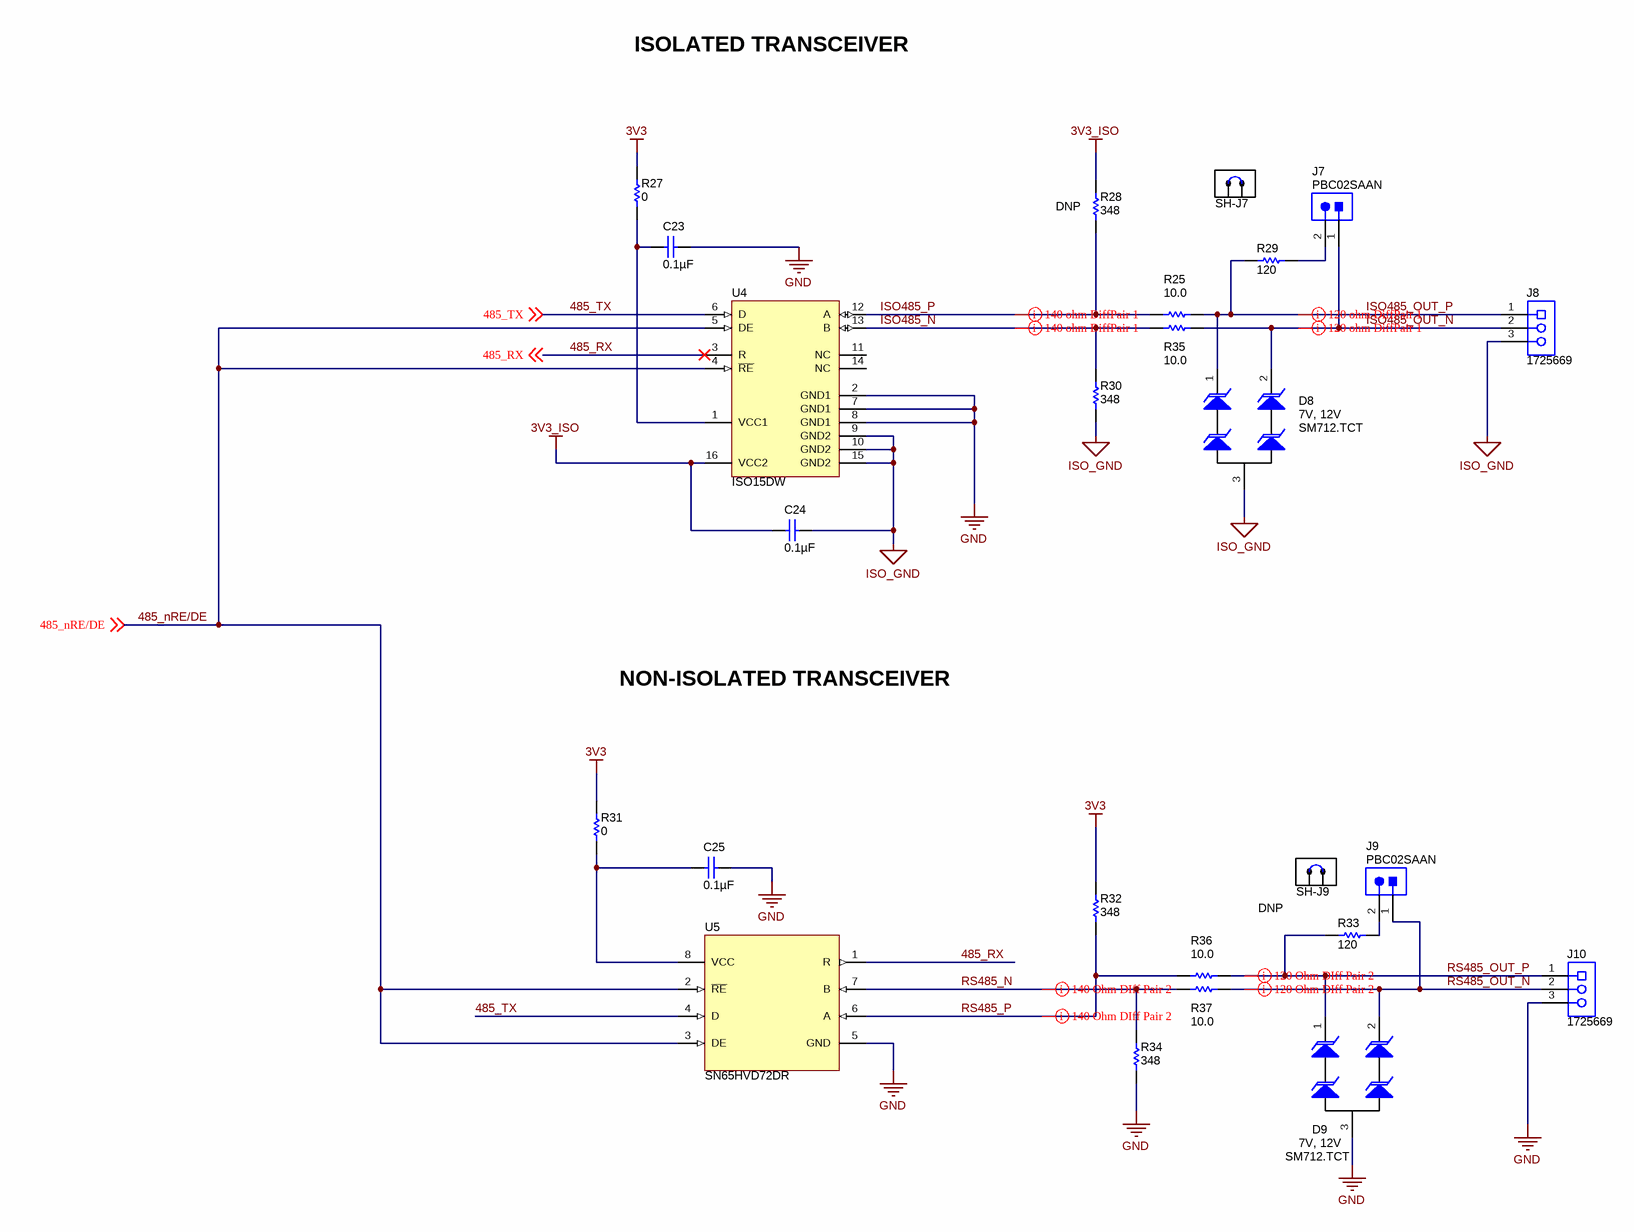
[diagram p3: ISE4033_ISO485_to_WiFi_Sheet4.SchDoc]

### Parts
C23  ValueDisplayed: 0.1µF  [0402]  (hidden comment: GRM155R71A104KA01D)
C24  ValueDisplayed: 0.1µF  [0402]  (hidden comment: GRM155R71A104KA01D)
C25  ValueDisplayed: 0.1µF  [0402]  (hidden comment: GRM155R71A104KA01D)
D8  value 7V, 12V  [SOT-23]  (hidden comment: SM712.TCT)
D9  value 7V, 12V  [SOT-23]  (hidden comment: SM712.TCT)
J7  PBC02SAAN  [Sullins_PBC02SAAN]
J8  1725669  [Phoenix_1725669]
J9  PBC02SAAN  [Sullins_PBC02SAAN]
J10  1725669  [Phoenix_1725669]
R25  ValueDisplayed: 10.0  [0402]  (hidden comment: CRCW040210R0FKED)
R27  ValueDisplayed: 0  [0603]  (hidden comment: CRCW06030000Z0EA)
R28  ValueDisplayed: 348  [0603]  (hidden comment: CRCW0603348RFKEA)
R29  ValueDisplayed: 120  [0603]  (hidden comment: RC0603FR-07120RL)
R30  ValueDisplayed: 348  [0603]  (hidden comment: CRCW0603348RFKEA)
R31  ValueDisplayed: 0  [0603]  (hidden comment: CRCW06030000Z0EA)
R32  ValueDisplayed: 348  [0603]  (hidden comment: CRCW0603348RFKEA)
R33  ValueDisplayed: 120  [0603]  (hidden comment: RC0603FR-07120RL)
R34  ValueDisplayed: 348  [0603]  (hidden comment: CRCW0603348RFKEA)
R35  ValueDisplayed: 10.0  [0402]  (hidden comment: CRCW040210R0FKED)
R36  ValueDisplayed: 10.0  [0402]  (hidden comment: CRCW040210R0FKED)
R37  ValueDisplayed: 10.0  [0402]  (hidden comment: CRCW040210R0FKED)
SH-J7  881545-2  [TE_881545-2]  (value not drawn)  (mechanical)
SH-J9  881545-2  [TE_881545-2]  (value not drawn)  (mechanical)
U4  ISO15DW  [DW0016A_N]
U5  SN65HVD72DR  [D0008A_N]

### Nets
3V3: R27.2 R31.2 R32.2
3V3_ISO: C24.2 R28.2 U4.16(VCC2)
GND: C23.1 C25.1 D9.3 J10.3 R34.1 U4.2(GND1) U4.7(GND1) U4.8(GND1) U5.5(GND)
ISO_GND: C24.1 D8.3 J8.3 R30.1 U4.9(GND2) U4.10(GND2) U4.15(GND2)
485_nRE/DE: U4.4(~{RE}) U4.5(DE) U5.2(~{RE}) U5.3(DE) ; off-sheet 485_nRE/DE
485_RX: U4.3(R) U5.1(R) ; off-sheet 485_RX
485_TX: U4.6(D) U5.4(D) ; off-sheet 485_TX
ISO485_N: R30.2 R35.1 U4.13(B)
ISO485_OUT_N: D8.2 J7.1 J8.2 R35.2
ISO485_OUT_P: D8.1 J8.1 R25.2 R29.1
ISO485_P: R25.1 R28.1 U4.12(A)
RS485_N: R34.2 R37.1 U5.7(B)
RS485_OUT_N: D9.2 J9.1 J10.2 R37.2
RS485_OUT_P: D9.1 J10.1 R33.1 R36.2
RS485_P: R32.1 R36.1 U5.6(A)
NetC23_2: C23.2 R27.1 U4.1(VCC1)
NetC25_2: C25.2 R31.1 U5.8(VCC)
NetJ7_2: J7.2 R29.2
NetJ9_2: J9.2 R33.2

Not connected (* = marked no-connect by the designer): U4 11(NC) 14(NC)

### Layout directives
differential pair: ISO485_N, ISO485_OUT_N, ISO485_OUT_P, ISO485_P, RS485_N, RS485_OUT_N, RS485_OUT_P, RS485_P

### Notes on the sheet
- ISOLATED TRANSCEIVER
- (near R28) DNP
- NON-ISOLATED TRANSCEIVER
- DNP

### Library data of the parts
C23-C25 = GRM155R71A104KA01D: as C16 on sheet ISE4033_ISO485_to_WiFi_Sheet2
D8 D9 = SM712.TCT: Asymmetrical TVS Diode for Extended Common-Mode RS-485, SOT-23; Manufacturer: Semtech; Symbol Creator: a0411947
J7 J9 = PBC02SAAN: as J6 on sheet ISE4033_ISO485_to_WiFi_Sheet3
J8 J10 = 1725669: Terminal Block, 3x1, 2.54 mm, TH; Manufacturer: Phoenix Contact; SymbolCreator: a0412235; U/M: EA
R25 R35-R37 = CRCW040210R0FKED: RES, 10.0, 1%, 0.063 W, 0402; Manufacturer: Vishay-Dale; CompType: Resistor; Value: 10.0; Res_ohm: 10; Value_Code: 10R0; Tolerance_%: 1; Power_W: 0.063; Value2: 0.063W; VDC_V: 50; TempCo: 100 ppm/C; EIA_Code: E96; U/M: EA
R27 R31 = CRCW06030000Z0EA: as R10 on sheet ISE4033_ISO485_to_WiFi_Sheet2
R28 R30 R32 R34 = CRCW0603348RFKEA: RES, 348, 1%, 0.1 W, 0603; Manufacturer: Vishay-Dale; CompType: Resistor; Value: 348; Value_Code: 348R; Tolerance_%: 1; Power_W: 0.1; Value2: 0.1W; VDC_V: 75; TempCo: 100 ppm/C; EIA_Code: E96; U/M: EA
R29 R33 = RC0603FR-07120RL: RES, 120, 1%, 0.1 W, 0603; Manufacturer: Yageo America; CompType: Resistor; Value: 120; Value_Code: 120R; Tolerance_%: 1; Power_W: 0.1; Value2: 0.1W; VDC_V: 150; TempCo: 200 ppm/C; U/M: EA
SH-J7 SH-J9 = 881545-2: as SH-J6 on sheet ISE4033_ISO485_to_WiFi_Sheet3
U4 = ISO15DW: Isolated 3.3 V RS-485 Transceiver, 1 Mbps, 3.3 V, Half Duplex, -40 to 85 degC, 16-pin SOIC (DW), Green (RoHS & no Sb/Br); Manufacturer: Texas Instruments; Alternate Manufacturer: None; Alternate PartNumber: Equivalent; # of TX/RX: 1 TX / 1 RX; Isolated: Yes; Number of Nodes: 256; Common Mode Range: -7 to 12; ESD(kV): 16; Fault Protection(V): -9 to 14; Fail Safe: Idle, Open, Short; ICC(Max)(mA): 21; Supply Voltage(s)(V): 3.3; Rating: Catalog
U5 = SN65HVD72DR: 3.3V-Supply RS-485 with IEC ESD Protection, D0008A; Manufacturer: Texas Instruments; SymbolCreator: a0411947; CompType: IC; U/M: EA

## Sheet ISE4033_ISO485_to_WiFi_Sheet5.SchDoc
size 431 x 279 mm; Date: Not shown in title block; ApprovedBy: Not shown in title block; CheckedBy: Not shown in title block; Author: Not shown in title block; CompanyName: Not shown in title block; Engineer: Not shown in title block; Organization: Not shown in title block; Address1: Not shown in title block; Address2: Not shown in title block; Address3: Not shown in title block; Address4: Not shown in title block; DocumentNumber: 1; Revision: Use project parameter SCH_Rev; SheetNumber: 5; SheetTotal: 6; PageSetup: Record=PageOptions¦CenterHorizontal=True¦CenterVertical=True¦PrintScale=1.00¦XCorrection=1.00¦YCorrection=1.00¦PrintKind=0¦BorderSize=5000000¦LeftOffset=0¦BottomOffset=0¦Orientation=2¦PaperLength=1000¦PaperWidth=1000¦Scale=100¦PaperSource=15¦PrintQuality=-3¦MediaType=1¦DitherType=10¦PrintScaleMode=1¦PaperKind=Tabloid (11 x 17")¦PaperIndex=17
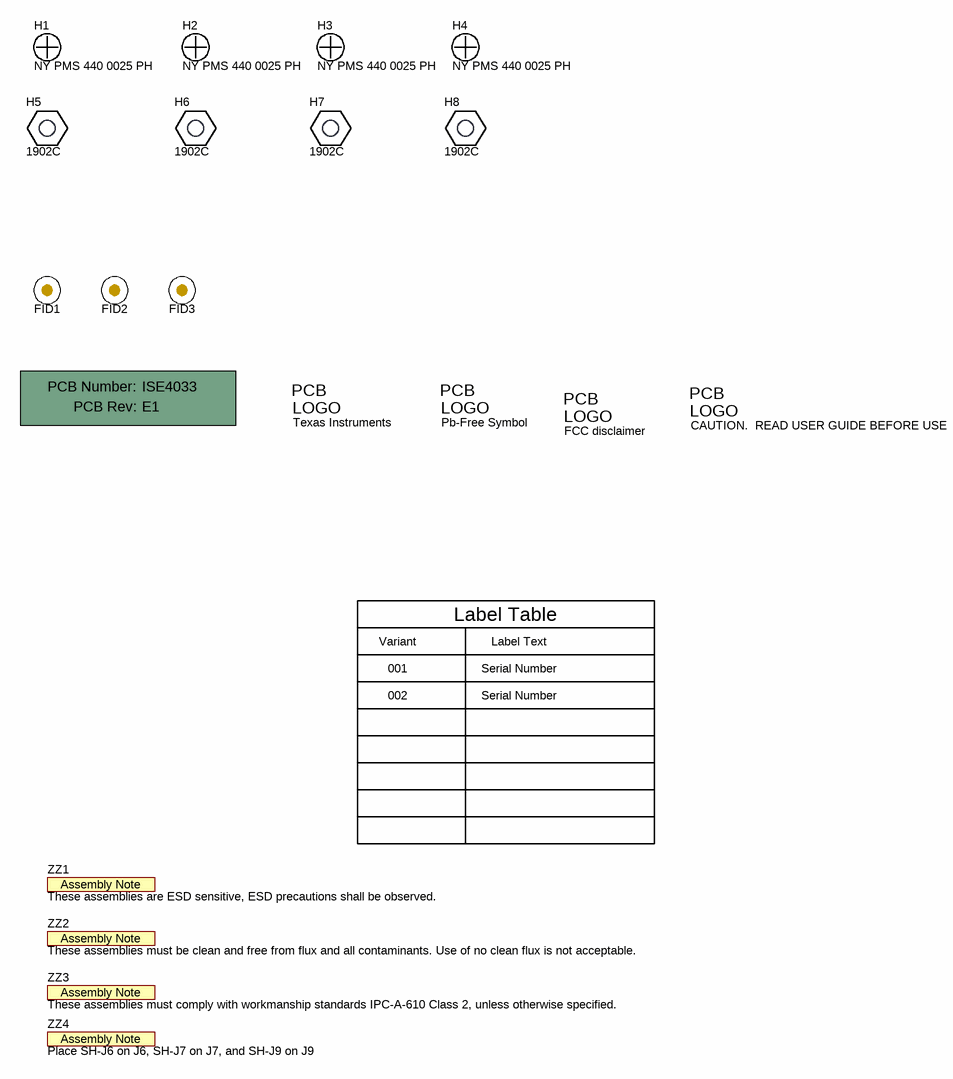
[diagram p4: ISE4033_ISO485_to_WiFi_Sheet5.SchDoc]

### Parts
!PCB1  Printed Circuit Board  (value not drawn)  (mechanical)
FID1  Fiducial  [Fiducial10-20]  (value not drawn)
FID2  Fiducial  [Fiducial10-20]  (value not drawn)
FID3  Fiducial  [Fiducial10-20]  (value not drawn)
H1  NY PMS 440 0025 PH  [NY PMS 440 0025 PH]
H2  NY PMS 440 0025 PH  [NY PMS 440 0025 PH]
H3  NY PMS 440 0025 PH  [NY PMS 440 0025 PH]
H4  NY PMS 440 0025 PH  [NY PMS 440 0025 PH]
H5  1902C  [Keystone_1902C]
H6  1902C  [Keystone_1902C]
H7  1902C  [Keystone_1902C]
H8  1902C  [Keystone_1902C]
Logo1  Texas Instruments  [TI_Stacked_Overlay_Small]  (no BOM)
Logo2  Pb-Free Symbol  [Pb-Free_Overlay_Small]  (no BOM)
Logo3  CAUTION.  READ USER GUIDE BEFORE USE  [IEC_Caution_Small]  (no BOM)
Logo4  FCC disclaimer  [FCC_disclaimer_stacked]  (no BOM)
ZZ1  These assemblies are ESD sensitive, ESD precautions shall be observed.  [AssemblyNote]  (no BOM)
ZZ2  These assemblies must be clean and free from flux and all contaminants. Use of no clean flux is not acceptable.  [AssemblyNote]  (no BOM)
ZZ3  These assemblies must comply with workmanship standards IPC-A-610 Class 2, unless otherwise specified.  [AssemblyNote]  (no BOM)
ZZ4  Place SH-J6 on J6, SH-J7 on J7, and SH-J9 on J9  [AssemblyNote]  (no BOM)

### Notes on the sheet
- Variant
- Label Table
- Label Text
- 001
- 002
- Serial Number

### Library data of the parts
!PCB1 = PCB: Manufacturer: Any; PartNumber: ISE4033; SymbolCreator: a0412235
FID1-FID3 = Fiducial: Fiducial mark.  There is nothing to buy or mount.; SymbolCreator: codlsc
H1-H4 = NY PMS 440 0025 PH: Machine Screw, Round, #4-40 x 1/4, Nylon, Philips panhead; Manufacturer: B&F Fastener Supply; CompType: Hardware; SymbolCreator: codlsc; U/M: EA
H5-H8 = 1902C: Standoff, Hex, 0.5"L #4-40 Nylon; Manufacturer: Keystone; CompType: Hardware
Logo1 = TI_Logo: Texas Instrument Corporate Signature; SymbolCreator: codlsc
Logo2 = Pb-Free: SymbolCreator: a0412235
Logo3 = IEC_Caution: IEC 61010-1 Caution Warning; SymbolCreator: a0412235
Logo4 = FCC_disclaimer: SymbolCreator: codlsc
ZZ1-ZZ4 = AssemblyNote: SymbolCreator: codlsc

## Sheet ISE4033E2_Sheet6.SchDoc
size 431 x 279 mm; Date: Not shown in title block; ApprovedBy: Not shown in title block; CheckedBy: Not shown in title block; Author: Not shown in title block; CompanyName: Not shown in title block; Engineer: Not shown in title block; Organization: Not shown in title block; Address1: Not shown in title block; Address2: Not shown in title block; Address3: Not shown in title block; Address4: Not shown in title block; DocumentNumber: 1; Revision: Use project parameter SCH_Rev; SheetNumber: 6; SheetTotal: 6; PageSetup: Record=PageOptions¦CenterHorizontal=True¦CenterVertical=True¦PrintScale=1.00¦XCorrection=1.00¦YCorrection=1.00¦PrintKind=0¦BorderSize=5000000¦LeftOffset=0¦BottomOffset=0¦Orientation=2¦PaperLength=1000¦PaperWidth=1000¦Scale=100¦PaperSource=15¦PrintQuality=600¦MediaType=1¦DitherType=10¦PaperKind=Letter¦PrintScaleMode=1
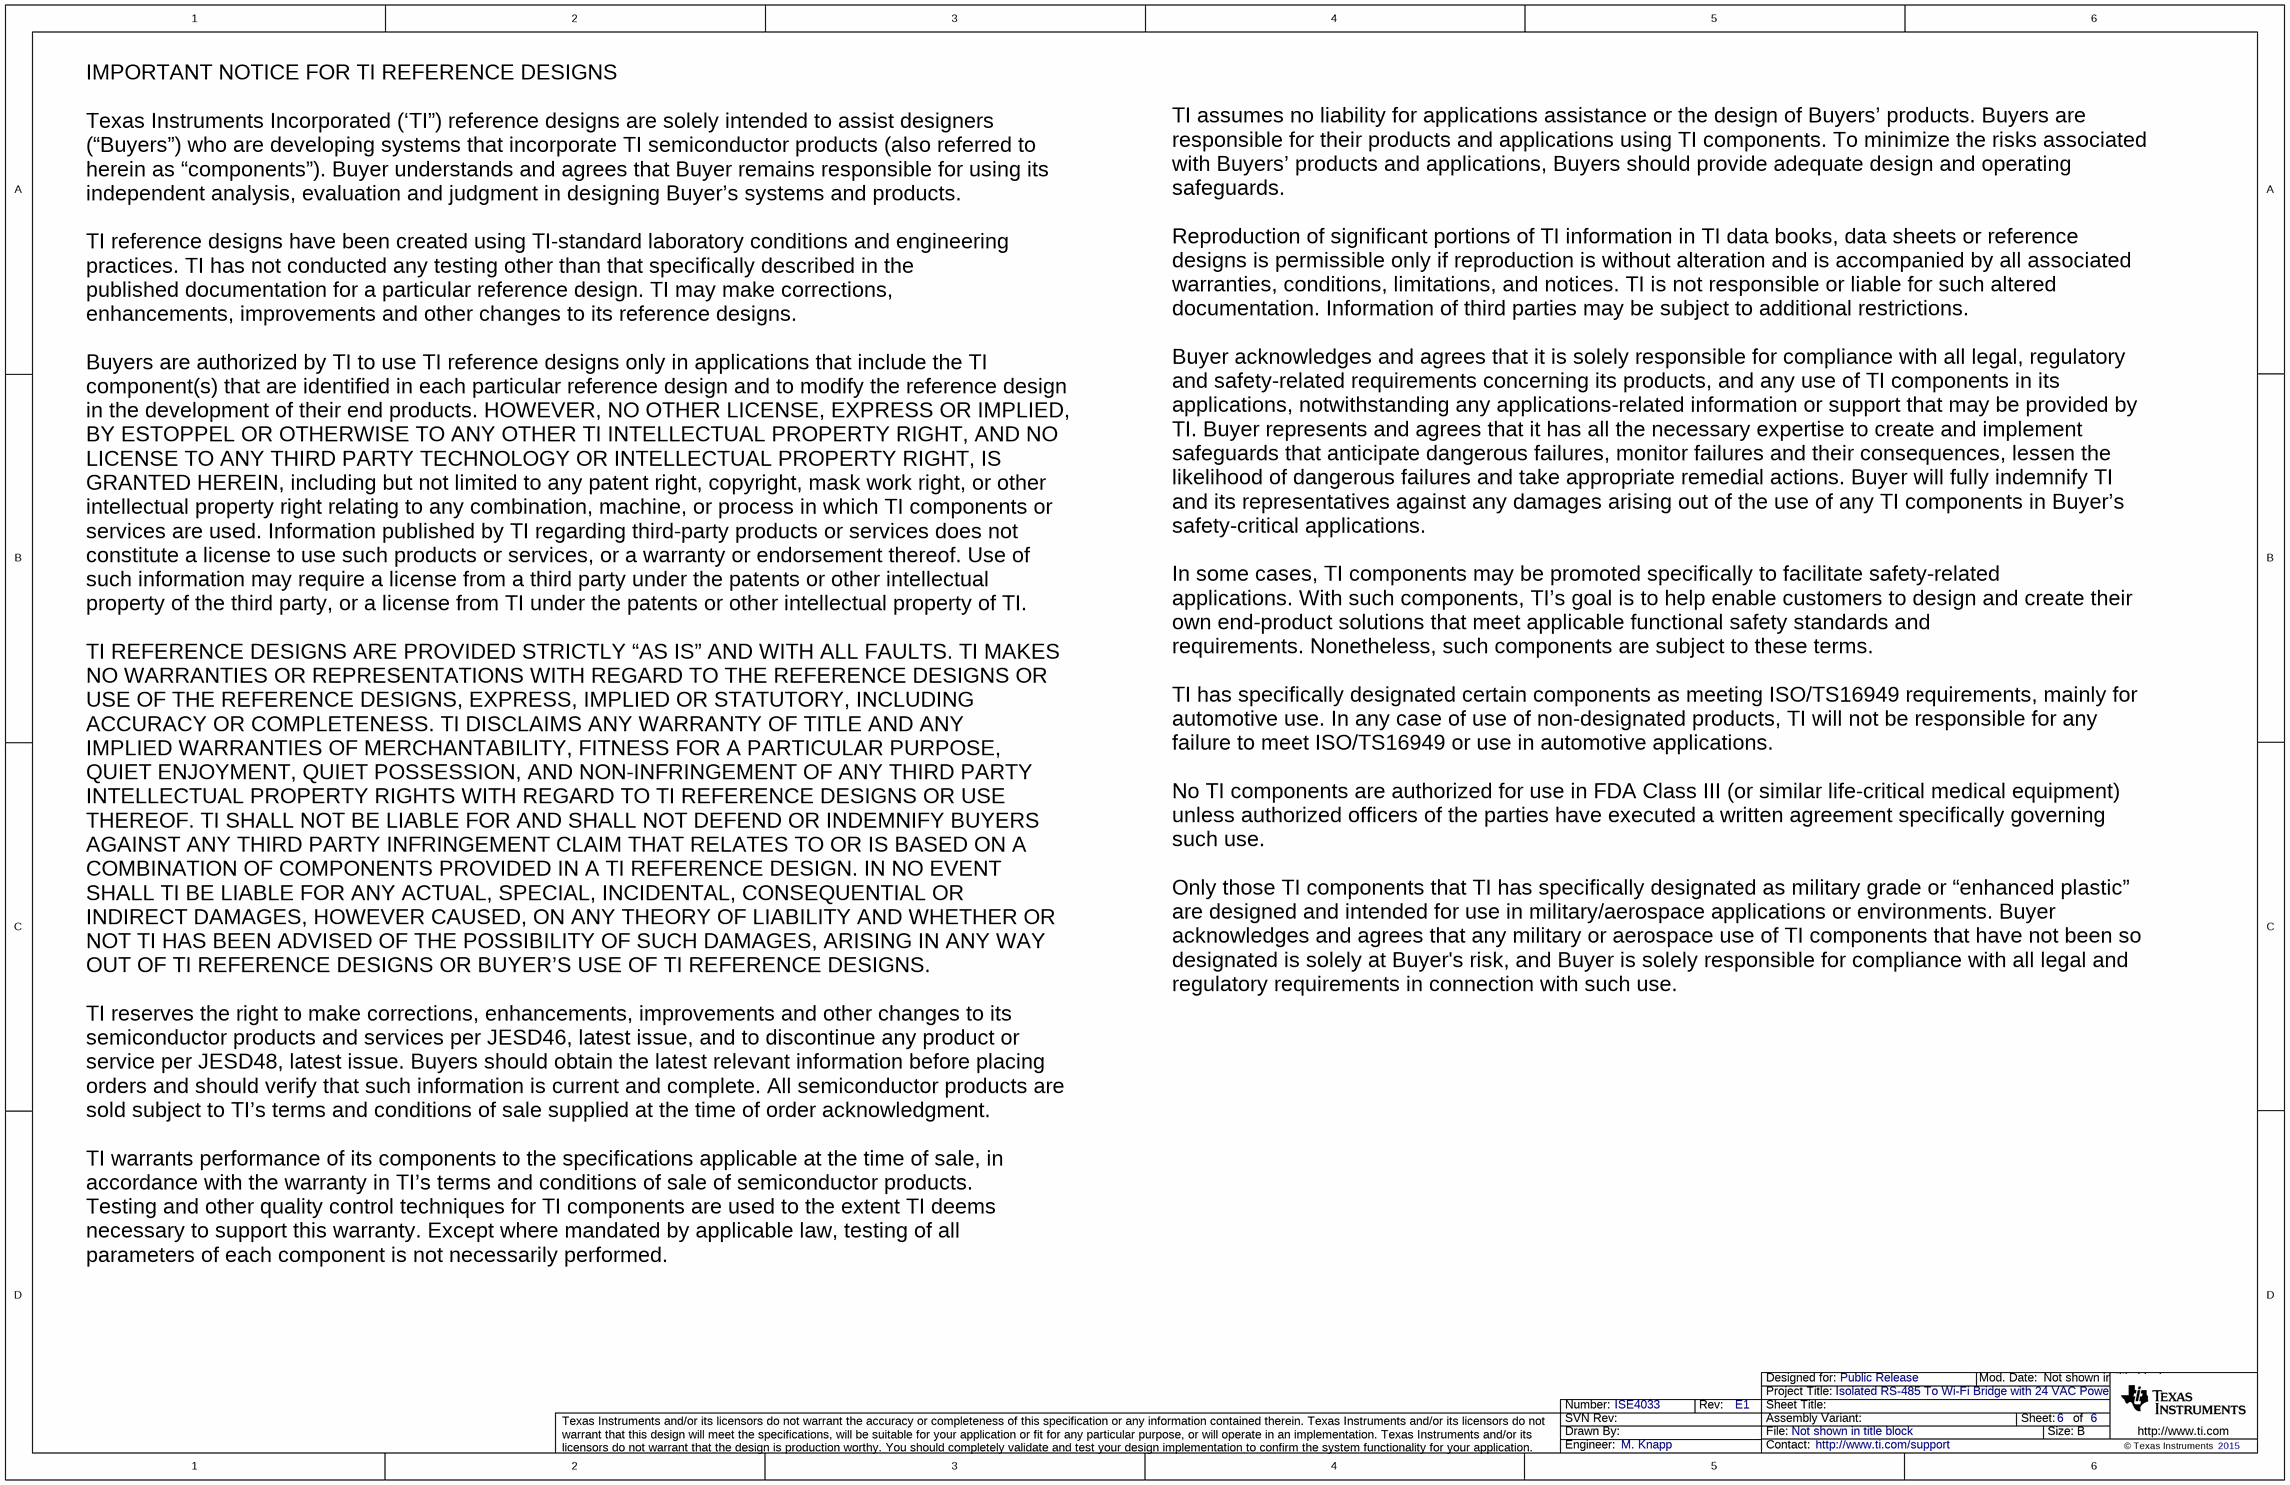
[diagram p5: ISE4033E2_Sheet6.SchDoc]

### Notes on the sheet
- IMPORTANT NOTICE FOR TI REFERENCE DESIGNS
  Texas Instruments Incorporated (‘TI”) reference designs are solely intended to assist designers
  (“Buyers”) who are developing systems that incorporate TI semiconductor products (also referred to
  herein as “components”). Buyer understands and agrees that Buyer remains responsible for using its
  independent analysis, evaluation and judgment in designing Buyer’s systems and products.
  TI reference designs have been created using TI-standard laboratory conditions and engineering
  practices. TI has not conducted any testing other than that specifically described in the
  published documentation for a particular reference design. TI may make corrections,
  enhancements, improvements and other changes to its reference designs.
  Buyers are authorized by TI to use TI reference designs only in applications that include the TI
  component(s) that are identified in each particular reference design and to modify the reference design
  in the development of their end products. HOWEVER, NO OTHER LICENSE, EXPRESS OR IMPLIED,
  BY ESTOPPEL OR OTHERWISE TO ANY OTHER TI INTELLECTUAL PROPERTY RIGHT, AND NO
  LICENSE TO ANY THIRD PARTY TECHNOLOGY OR INTELLECTUAL PROPERTY RIGHT, IS
  GRANTED HEREIN, including but not limited to any patent right, copyright, mask work right, or other
  intellectual property right relating to any combination, machine, or process in which TI components or
  services are used. Information published by TI regarding third-party products or services does not
  constitute a license to use such products or services, or a warranty or endorsement thereof. Use of
  such information may require a license from a third party under the patents or other intellectual
  property of the third party, or a license from TI under the patents or other intellectual property of TI.
  TI REFERENCE DESIGNS ARE PROVIDED STRICTLY “AS IS” AND WITH ALL FAULTS. TI MAKES
  NO WARRANTIES OR REPRESENTATIONS WITH REGARD TO THE REFERENCE DESIGNS OR
  USE OF THE REFERENCE DESIGNS, EXPRESS, IMPLIED OR STATUTORY, INCLUDING
  ACCURACY OR COMPLETENESS. TI DISCLAIMS ANY WARRANTY OF TITLE AND ANY
  IMPLIED WARRANTIES OF MERCHANTABILITY, FITNESS FOR A PARTICULAR PURPOSE,
  QUIET ENJOYMENT, QUIET POSSESSION, AND NON-INFRINGEMENT OF ANY THIRD PARTY
  INTELLECTUAL PROPERTY RIGHTS WITH REGARD TO TI REFERENCE DESIGNS OR USE
  THEREOF. TI SHALL NOT BE LIABLE FOR AND SHALL NOT DEFEND OR INDEMNIFY BUYERS
  AGAINST ANY THIRD PARTY INFRINGEMENT CLAIM THAT RELATES TO OR IS BASED ON A
  COMBINATION OF COMPONENTS PROVIDED IN A TI REFERENCE DESIGN. IN NO EVENT
  SHALL TI BE LIABLE FOR ANY ACTUAL, SPECIAL, INCIDENTAL, CONSEQUENTIAL OR
  INDIRECT DAMAGES, HOWEVER CAUSED, ON ANY THEORY OF LIABILITY AND WHETHER OR
  NOT TI HAS BEEN ADVISED OF THE POSSIBILITY OF SUCH DAMAGES, ARISING IN ANY WAY
  OUT OF TI REFERENCE DESIGNS OR BUYER’S USE OF TI REFERENCE DESIGNS.
  TI reserves the right to make corrections, enhancements, improvements and other changes to its
  semiconductor products and services per JESD46, latest issue, and to discontinue any product or
  service per JESD48, latest issue. Buyers should obtain the latest relevant information before placing
  orders and should verify that such information is current and complete. All semiconductor products are
  sold subject to TI’s terms and conditions of sale supplied at the time of order acknowledgment.
  TI warrants performance of its components to the specifications applicable at the time of sale, in
  accordance with the warranty in TI’s terms and conditions of sale of semiconductor products.
  Testing and other quality control techniques for TI components are used to the extent TI deems
  necessary to support this warranty. Except where mandated by applicable law, testing of all
  parameters of each component is not necessarily performed.
- TI assumes no liability for applications assistance or the design of Buyers’ products. Buyers are
  responsible for their products and applications using TI components. To minimize the risks associated
  with Buyers’ products and applications, Buyers should provide adequate design and operating
  safeguards.
  Reproduction of significant portions of TI information in TI data books, data sheets or reference
  designs is permissible only if reproduction is without alteration and is accompanied by all associated
  warranties, conditions, limitations, and notices. TI is not responsible or liable for such altered
  documentation. Information of third parties may be subject to additional restrictions.
  Buyer acknowledges and agrees that it is solely responsible for compliance with all legal, regulatory
  and safety-related requirements concerning its products, and any use of TI components in its
  applications, notwithstanding any applications-related information or support that may be provided by
  TI. Buyer represents and agrees that it has all the necessary expertise to create and implement
  safeguards that anticipate dangerous failures, monitor failures and their consequences, lessen the
  likelihood of dangerous failures and take appropriate remedial actions. Buyer will fully indemnify TI
  and its representatives against any damages arising out of the use of any TI components in Buyer’s
  safety-critical applications.
  In some cases, TI components may be promoted specifically to facilitate safety-related
  applications. With such components, TI’s goal is to help enable customers to design and create their
  own end-product solutions that meet applicable functional safety standards and
  requirements. Nonetheless, such components are subject to these terms.
  TI has specifically designated certain components as meeting ISO/TS16949 requirements, mainly for
  automotive use. In any case of use of non-designated products, TI will not be responsible for any
  failure to meet ISO/TS16949 or use in automotive applications.
  No TI components are authorized for use in FDA Class III (or similar life-critical medical equipment)
  unless authorized officers of the parties have executed a written agreement specifically governing
  such use.
  Only those TI components that TI has specifically designated as military grade or “enhanced plastic”
  are designed and intended for use in military/aerospace applications or environments. Buyer
  acknowledges and agrees that any military or aerospace use of TI components that have not been so
  designated is solely at Buyer's risk, and Buyer is solely responsible for compliance with all legal and
  regulatory requirements in connection with such use.

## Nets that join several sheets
3V3: ISE4033_ISO485_to_WiFi_Sheet2 (D5.1 R4.2), ISE4033_ISO485_to_WiFi_Sheet3 (11 pins), ISE4033_ISO485_to_WiFi_Sheet4 (R27.2 R31.2 R32.2)
3V3_ISO: ISE4033_ISO485_to_WiFi_Sheet2 (C15.1 TP13.1 U2.5), ISE4033_ISO485_to_WiFi_Sheet4 (C24.2 R28.2 U4.16)
GND: ISE4033_ISO485_to_WiFi_Sheet2 (18 pins), ISE4033_ISO485_to_WiFi_Sheet3 (48 pins), ISE4033_ISO485_to_WiFi_Sheet4 (9 pins)
ISO_GND: ISE4033_ISO485_to_WiFi_Sheet2 (8 pins), ISE4033_ISO485_to_WiFi_Sheet4 (7 pins)
485_nRE/DE: ISE4033_ISO485_to_WiFi_Sheet3 (R18.2 U3.50), ISE4033_ISO485_to_WiFi_Sheet4 (U4.4 U4.5 U5.2 U5.3)
485_RX: ISE4033_ISO485_to_WiFi_Sheet3 (TP10.1 U3.49), ISE4033_ISO485_to_WiFi_Sheet4 (U4.3 U5.1)
485_TX: ISE4033_ISO485_to_WiFi_Sheet3 (R17.1 TP9.1 U3.48), ISE4033_ISO485_to_WiFi_Sheet4 (U4.6 U5.4)

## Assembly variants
001: not fitted C11 C17 C25 D9 FID1 FID2 FID3 J2 J9 J10 L2 L3 R13 R31 R32 R33 R34 R36 R37 SH-J9 U5
002: not fitted C6 C7 C11 C15 C16 C17 C23 C24 D3 D8 FID1 FID2 FID3 J2 J7 J8 L3 R2 R10 R13 R25 R27 R28 R29 R30 R35 SH-J7 T1 TP11 TP12 TP13 U2 U4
